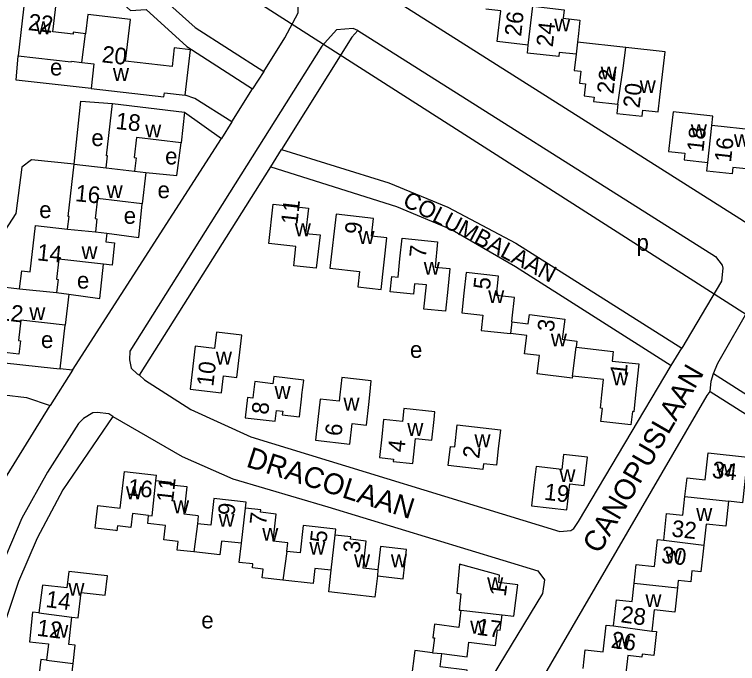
# Model space of a CAD drawing. Extents: x 161936 to 163647, y 386450 to 388633.
# Drawn here: x 162752.9 to 162926.6, y 386685.5 to 386841.4 of the extents above; entities that cross this region are included whole.
import ezdxf

# ---------------------------------------------------------------- set-up
doc = ezdxf.new("R2010")
doc.units = 0
for name, color, linetype in [('BLT_Basislijn', 7, 'Continuous'), ('BLT_Bebouwing', 7, 'Continuous'), ('BLT_Centroide', 7, 'Continuous'), ('BLT_Hoogspanningsmast_en_leidingen', 7, 'Continuous'), ('BLT_Huisnummer', 7, 'Continuous'), ('BLT_Huisnummer_ tussenligend', 7, 'Continuous'), ('BLT_Onderverdeling_panden', 7, 'Continuous'), ('BLT_Straatnaam', 7, 'Continuous'), ('BLT_Straatnaam_verkleind', 7, 'Continuous')]:
    doc.layers.add(name, color=color, linetype=linetype)

msp = doc.modelspace()

# ---------------------------------------------------------------- linework, layer by layer
at = {"layer": 'BLT_Basislijn'}
for p, q in [((162812.79, 386827.68), (162810.14, 386823.51)), ((162805.16, 386815.58), (162810.14, 386823.51)), ((162793.8, 386817.95), (162802.65, 386811.57)), ((162805.16, 386815.58), (162802.65, 386811.57)), ((162766.85, 386755.96), (162802.65, 386811.57)), ((162814.47, 386804.76), (162817.03, 386808.96)), ((162782.93, 386754.74), (162814.47, 386804.76)), ((162763.95, 386756.26), (162765.14, 386766.74)), ((162910.66, 386757.07), (162913.17, 386761.25)), ((162766.85, 386755.96), (162761.5, 386747.49)), ((162766.85, 386755.96), (162763.95, 386756.26)), ((162920.79, 386755.11), (162990.3, 386711.09))]:
    msp.add_line(p, q, dxfattribs=at)
for points in [[(162936.8, 386857.14), (162935.32, 386858.78), (162933.64, 386862.63), (162935.1, 386879.01), (162937.86, 386902.98), (162937.81, 386905.48), (162935.4, 386907.84), (162904.46, 386923.62), (162901.57, 386924.93), (162898.79, 386924.8), (162897.86, 386924.36), (162886.94, 386910.11), (162842.13, 386849.46), (162842.02, 386847.45), (162842.46, 386846.29), (162843.42, 386845.43), (162927.11, 386792.36), (162929.58, 386790.79)], [(162764.7, 386883.35), (162761.89, 386878.93), (162762.37, 386864.79), (162781.5, 386847.61), (162782.13, 386847.17), (162786.38, 386847.26), (162796.3, 386838.28), (162812.79, 386827.68)], [(162812.79, 386827.68), (162817.86, 386835.81), (162821.06, 386841.79), (162821, 386845.16), (162820.58, 386846.26), (162818.29, 386849.14), (162764.7, 386883.35)], [(162759.38, 386861.14), (162764.81, 386856.95), (162780.78, 386842.31), (162784.57, 386842.55), (162794.31, 386833.67), (162810.14, 386823.51)], [(162835.41, 386837.55), (162834.27, 386838.02), (162830.29, 386837.68), (162826.79, 386833.75), (162780.68, 386760.55), (162780.59, 386758.42), (162781, 386756.44), (162782.41, 386755.03), (162782.93, 386754.74)], [(162835.41, 386837.55), (162833.98, 386835.94), (162817.03, 386808.96)], [(162835.41, 386837.55), (162921.26, 386783.25), (162922.87, 386781.16), (162923.08, 386780.45), (162922.76, 386777.33), (162913.17, 386761.25)], [(162771.34, 386823.63), (162753.36, 386825.59), (162753.86, 386831.46)], [(162805.16, 386815.58), (162796.23, 386821.24), (162793.92, 386822)], [(162767.29, 386805.44), (162768.91, 386820.58), (162776.51, 386819.97)], [(162784.51, 386803.46), (162791.97, 386802.73), (162792.94, 386810.58)], [(162817.03, 386808.96), (162842.87, 386800.98), (162857.03, 386795.09), (162873.33, 386786.43), (162913.17, 386761.25)], [(162767.29, 386805.44), (162757.02, 386806.44), (162754.73, 386804.72), (162753.3, 386793.58), (162740.88, 386774.54), (162739.9, 386760.72), (162741.39, 386758.8), (162745.4, 386758.23), (162746.76, 386758.08)], [(162814.47, 386804.76), (162844.71, 386795.25), (162858.05, 386789.62), (162873.26, 386780.84), (162910.66, 386757.07)], [(162775.15, 386788.83), (162782.77, 386787.83), (162783.63, 386795.93)], [(162766.01, 386774.23), (162773.43, 386773.18), (162774.29, 386781.41)], [(162920.79, 386755.11), (162921.83, 386757.64), (162930.08, 386772.01), (162932.53, 386774.04), (162936.13, 386773.99), (162999.95, 386732.91), (163001.7, 386730.64), (163001.7, 386727.45), (162990.3, 386711.09)], [(162746.76, 386758.08), (162762.29, 386756.42), (162763.95, 386756.26)], [(162782.93, 386754.74), (162784.14, 386753.62), (162795.28, 386746.49), (162809.67, 386739.93), (162883.93, 386717.19), (162886.57, 386717.43), (162887.27, 386717.9), (162888.41, 386719.58), (162910.66, 386757.07)], [(162920.03, 386750.79), (162920.27, 386753.27), (162920.79, 386755.11)], [(162790.57, 386600.78), (162790.73, 386604.36), (162795.98, 386649.72), (162796.62, 386650.92), (162798.46, 386652.65), (162801.59, 386653.16), (162862.7, 386652.56), (162919.26, 386749.89), (162920.03, 386750.79)], [(162920.03, 386750.79), (162979.99, 386712.91), (162982.39, 386711.29), (162982.96, 386709.97), (162926.1, 386645.24), (162880.32, 386594.41)], [(162750.43, 386750), (162755.86, 386749.4), (162761.5, 386747.49)], [(162728.43, 386670.51), (162736.88, 386695.49), (162740.37, 386707.4), (162746.01, 386721.18), (162749.44, 386728.03), (162761.5, 386747.49)], [(162776.6, 386744.83), (162775.59, 386745.44), (162772.77, 386745.82), (162771.8, 386745.7), (162769.54, 386744.35), (162768.33, 386743.18), (162760.9, 386731.43), (162754.74, 386720.41), (162748.33, 386705.49), (162725.09, 386634.99), (162722.73, 386620.46), (162722.23, 386607.04), (162723.34, 386603.79), (162724.64, 386602.11), (162726.53, 386600.36), (162729.65, 386599.25), (162771.09, 386596.47), (162775.81, 386597.36), (162778.89, 386601.28)], [(162776.6, 386744.83), (162764.56, 386727.23), (162758.39, 386715.61), (162753.9, 386705.17), (162742.91, 386672.59)], [(162776.6, 386744.83), (162793.21, 386735.25), (162805.37, 386729.84), (162828.22, 386723.15), (162878.61, 386707.72), (162880.2, 386705.59), (162879.76, 386702.34), (162857.19, 386665.08), (162855.02, 386663.16), (162851.68, 386662.44), (162793.61, 386662.98)]]:
    msp.add_lwpolyline(points, dxfattribs=at)
at = {"layer": 'BLT_Bebouwing'}
for p, q in [((162755.84, 386848.89), (162753.86, 386831.46)), ((162899.74, 386833.48), (162888.13, 386834.76)), ((162776.51, 386819.97), (162793.8, 386817.95)), ((162793.8, 386817.95), (162792.94, 386810.58)), ((162920.43, 386814.75), (162920.68, 386816.96)), ((162931.98, 386813.46), (162920.43, 386814.75)), ((162767.29, 386805.44), (162774.94, 386804.55)), ((162781.79, 386803.78), (162784.51, 386803.46)), ((162784.51, 386803.46), (162783.63, 386795.93)), ((162772.37, 386789.15), (162775.15, 386788.83)), ((162763.07, 386774.58), (162766.01, 386774.23)), ((162766.01, 386774.23), (162765.14, 386766.74)), ((162786.93, 386729.4), (162787.08, 386730.76)), ((162808.42, 386722.81), (162808.58, 386724.27)), ((162797.08, 386721), (162796.86, 386719.06))]:
    msp.add_line(p, q, dxfattribs=at)
for points in [[(162770.02, 386836.77), (162767.07, 386837.1), (162767.02, 386836.66), (162762.16, 386837.21), (162763.4, 386848.03), (162755.84, 386848.89)], [(162876.33, 386834.04), (162868.88, 386834.89), (162869.72, 386842.26), (162866.14, 386842.66)], [(162877.39, 386843.36), (162884.91, 386842.51), (162884.68, 386840.48), (162888.73, 386840.02), (162888.36, 386836.79), (162888.13, 386834.77)], [(162793.92, 386822), (162795.18, 386832.93), (162791.3, 386833.37), (162790.79, 386828.92), (162779.64, 386830.2), (162780.78, 386840.22), (162770.55, 386841.39), (162770.02, 386836.77)], [(162887.79, 386831.82), (162883.77, 386832.28), (162883.65, 386831.26), (162876.11, 386832.12), (162876.33, 386834.04)], [(162897.83, 386819.81), (162897.58, 386817.61), (162903.66, 386816.93), (162903.83, 386818.41), (162907.55, 386817.99), (162907.95, 386821.51), (162909.17, 386832.44), (162899.74, 386833.48)], [(162753.86, 386831.46), (162766.59, 386830.01), (162766.61, 386830.18), (162769.15, 386829.89)], [(162887.79, 386831.82), (162887.35, 386827.94), (162888.98, 386827.75), (162888.66, 386824.86), (162890.05, 386824.71), (162889.77, 386821.81), (162892.12, 386821.55), (162891.99, 386820.46), (162897.83, 386819.81)], [(162769.15, 386829.89), (162772.01, 386829.56), (162771.34, 386823.63)], [(162771.34, 386823.63), (162788.85, 386821.64), (162788.96, 386822.57), (162793.92, 386822)], [(162774.94, 386804.55), (162775.27, 386807.44), (162775.05, 386807.47), (162776.51, 386819.97)], [(162920.68, 386816.96), (162911.1, 386818.02), (162910.43, 386811.98), (162910.04, 386808.48), (162913.9, 386808.05), (162913.73, 386806.5), (162919.45, 386805.87)], [(162792.94, 386810.58), (162782.27, 386811.82), (162781.71, 386807), (162782.16, 386806.94), (162781.79, 386803.78)], [(162765.7, 386789.82), (162766.05, 386792.83), (162765.82, 386792.85), (162767.29, 386805.44)], [(162930.94, 386804.04), (162925.45, 386804.65), (162925.28, 386803.12), (162919.22, 386803.79), (162919.45, 386805.87)], [(162783.63, 386795.93), (162772.89, 386797.18), (162772.33, 386792.35), (162772.74, 386792.3), (162772.37, 386789.15)], [(162820, 386781.03), (162820.51, 386785.65), (162814.05, 386786.37), (162815.09, 386795.8), (162823.54, 386794.86), (162822.87, 386788.81), (162826.32, 386788.43), (162825.43, 386780.43), (162820, 386781.03)], [(162842.38, 386787.74), (162838.71, 386788.15), (162839.19, 386792.4), (162830.16, 386793.42), (162828.7, 386780.49), (162835.83, 386779.68), (162835.4, 386775.93), (162840.97, 386775.3), (162842.38, 386787.74)], [(162754.19, 386775.52), (162754.69, 386779.84), (162756.68, 386779.61), (162757.98, 386790.73), (162765.7, 386789.82)], [(162775.15, 386788.83), (162774.91, 386786.74), (162777, 386786.5), (162776.37, 386781.16), (162774.29, 386781.41)], [(162856.98, 386775.39), (162856.44, 386770.1), (162851.27, 386770.63), (162851.86, 386776.43), (162849.03, 386776.72), (162848.78, 386774.22), (162843.16, 386774.79), (162843.53, 386778.42), (162845.06, 386778.26), (162845.51, 386782.66), (162846.02, 386787.64), (162854.54, 386786.77), (162853.93, 386780.73), (162857.49, 386780.37), (162856.98, 386775.39)], [(162774.29, 386781.41), (162763.59, 386782.65), (162763.02, 386777.8), (162763.44, 386777.75), (162763.07, 386774.58)], [(162872.48, 386768.42), (162873.04, 386773.39), (162868.69, 386773.88), (162869.21, 386778.56), (162861.44, 386779.43), (162860.89, 386774.46), (162860.36, 386769.71), (162865.45, 386769.14), (162865.04, 386765.5), (162872.07, 386764.72)], [(162747.11, 386760.63), (162747.46, 386763.64), (162747.21, 386763.67), (162748.67, 386776.16), (162754.19, 386775.52)], [(162765.14, 386766.74), (162754.49, 386767.99), (162753.92, 386763.08), (162754.36, 386763.03), (162753.99, 386759.82), (162747.11, 386760.63)], [(162872.39, 386767.55), (162876.34, 386767.08), (162876.63, 386769.32), (162885.11, 386768.23), (162884.48, 386763.36), (162888, 386762.91), (162887.81, 386761.44)], [(162872.39, 386767.55), (162872.48, 386768.42)], [(162795.11, 386751.39), (162802.67, 386750.51), (162803.14, 386754.59), (162806.35, 386754.22), (162807.53, 386764.39), (162801.45, 386765.09), (162801, 386761.19), (162796.3, 386761.74), (162795.11, 386751.39)], [(162886.91, 386754.49), (162886.85, 386754.02), (162878.47, 386755.1), (162879.03, 386759.44), (162875.42, 386759.9), (162875.98, 386764.28), (162872.07, 386764.72)], [(162887.81, 386761.44), (162896.74, 386760.46), (162896.49, 386758.15), (162902.9, 386757.45), (162902.09, 386750)], [(162821.95, 386749.73), (162821.98, 386750), (162822.41, 386753.56), (162815.2, 386754.42), (162814.99, 386752.68), (162810.68, 386753.19), (162810.3, 386750), (162810.21, 386749.22), (162808.94, 386749.37), (162808.37, 386744.54), (162815.53, 386743.69), (162815.84, 386746.29), (162817.35, 386746.11), (162817.25, 386745.25), (162821.36, 386744.76), (162821.95, 386749.73)], [(162838, 386747.73), (162838.25, 386750), (162838.62, 386753.38), (162831.56, 386754.16), (162831.1, 386750), (162830.94, 386748.5), (162826.35, 386749.01), (162825.81, 386744.07), (162825.26, 386739.1), (162833.5, 386738.2), (162834.04, 386743.13), (162837.45, 386742.76), (162838, 386747.73)], [(162902.09, 386750), (162901.65, 386745.96), (162901.36, 386745.99), (162900.93, 386742.82), (162893.76, 386743.66), (162894.12, 386746.77), (162893.68, 386746.83), (162894.02, 386750), (162894.43, 386753.67), (162886.91, 386754.49)], [(162853.72, 386744.1), (162853.92, 386745.94), (162846.46, 386746.75), (162846.12, 386743.6), (162841.59, 386744.09), (162841.14, 386739.93), (162840.6, 386734.96), (162843.97, 386734.6), (162843.91, 386734.05), (162848.59, 386733.54), (162849.24, 386739.55), (162853.18, 386739.13), (162853.72, 386744.1)], [(162869.65, 386741.58), (162869.13, 386737.05), (162868.67, 386733.13), (162865.61, 386733.48), (162865.45, 386732.11), (162857.12, 386733.08), (162857.65, 386737.64), (162858.67, 386737.52), (162859.28, 386742.78), (162869.65, 386741.58)], [(162884.81, 386735.73), (162884.39, 386732.09), (162878.21, 386732.8), (162877.7, 386728.35), (162877.13, 386723.38), (162885.58, 386722.41), (162886.29, 386728.61), (162889.74, 386728.22), (162890.52, 386735.08), (162884.81, 386735.73)], [(162913.96, 386725.6), (162914.45, 386730.09), (162918.81, 386729.62), (162919.52, 386736.12), (162928.96, 386735.09), (162928.42, 386730.11), (162928.24, 386728.48), (162927.77, 386724.09), (162924.44, 386724.46)], [(162785.16, 386721.08), (162781.29, 386721.52), (162780.91, 386718.18), (162777.68, 386718.54), (162777.55, 386717.37), (162777.32, 386717.4), (162772.35, 386717.96), (162772.96, 386723.41), (162778.35, 386722.8), (162779.34, 386731.63), (162787.08, 386730.76)], [(162797.08, 386721), (162793.67, 386721.38), (162794.41, 386727.9), (162790.53, 386728.34), (162790.6, 386728.99), (162786.93, 386729.4)], [(162808.58, 386724.27), (162800.81, 386725.14), (162800.08, 386718.69), (162796.86, 386719.06)], [(162908.85, 386715.14), (162909.55, 386721.54), (162913.47, 386721.11), (162913.96, 386725.6)], [(162818.34, 386712.42), (162818.57, 386714.45), (162815.05, 386714.85), (162815.79, 386721.39), (162812.06, 386721.81), (162812.13, 386722.4), (162808.42, 386722.81)], [(162924.44, 386724.46), (162923.79, 386718.45), (162919.02, 386718.97), (162918.46, 386713.89)], [(162795.98, 386712.28), (162792.01, 386712.73), (162792.24, 386714.78), (162788.78, 386715.17), (162789.18, 386718.65), (162784.94, 386719.12), (162785.16, 386721.08)], [(162829.96, 386716.35), (162830.12, 386717.74), (162822.26, 386718.62), (162821.52, 386712.06), (162818.34, 386712.42)], [(162840.23, 386707.97), (162836.69, 386708.37), (162837.43, 386714.9), (162833.65, 386715.33), (162833.72, 386715.93), (162829.96, 386716.35)], [(162807.46, 386714.36), (162802.65, 386714.9), (162802.28, 386711.57), (162795.98, 386712.28)], [(162817.39, 386705.52), (162812.44, 386706.08), (162812.68, 386708.18), (162810.08, 386708.47), (162810.19, 386709.4), (162806.94, 386709.77), (162807.46, 386714.36)], [(162901.78, 386704.81), (162902.27, 386709.25), (162906.62, 386708.78), (162907.33, 386715.3), (162908.85, 386715.14)], [(162840.1, 386706.54), (162846.31, 386705.83), (162847.1, 386712.87)], [(162847.1, 386712.87), (162840.82, 386713.58), (162840.23, 386707.97)], [(162918.46, 386713.89), (162917.76, 386707.49), (162915.63, 386707.72), (162915.34, 386705.11), (162912.33, 386705.44), (162912.13, 386703.68)], [(162859.8, 386709.35), (162859.14, 386702.36), (162860.15, 386702.25), (162859.73, 386698.34), (162860.15, 386698.29)], [(162870.02, 386697.2), (162872.84, 386696.83), (162873.84, 386704.38), (162869.23, 386704.97), (162869.43, 386706.71), (162859.8, 386709.35)], [(162766.7, 386696.65), (162768.21, 386696.48), (162768.92, 386702.55), (162774.74, 386701.87), (162775.28, 386706.52), (162772.97, 386706.79), (162770.96, 386707.03), (162765.99, 386707.61), (162765.53, 386703.65), (162759.64, 386704.34), (162758.82, 386697.65)], [(162829, 386707.89), (162825.09, 386708.33), (162824.68, 386704.7), (162817.39, 386705.52)], [(162840.1, 386706.54), (162839.52, 386701.44), (162828.41, 386702.69), (162829, 386707.89)], [(162896.79, 386694.54), (162897.48, 386700.79), (162901.3, 386700.37), (162901.78, 386704.81)], [(162912.13, 386703.68), (162911.5, 386697.86), (162906.57, 386698.41), (162906, 386693.29)], [(162758.82, 386697.65), (162757.29, 386697.81), (162756.53, 386690.68), (162761.09, 386690.2), (162760.67, 386686.33)], [(162860.15, 386698.29), (162859.63, 386694.16), (162853.8, 386694.91), (162853.39, 386691.67), (162853.77, 386691.62), (162853.31, 386688.09)], [(162855.54, 386687.87), (162861.62, 386687.09), (162862.07, 386690.62), (162868.48, 386689.79), (162868.97, 386693.61), (162869.55, 386693.53), (162870.02, 386697.2)], [(162767.03, 386685.52), (162767.49, 386689.87), (162765.99, 386690.03), (162766.7, 386696.65)], [(162889.49, 386684.3), (162889.99, 386688.79), (162894.3, 386688.31), (162895.02, 386694.74), (162896.79, 386694.54)], [(162906, 386693.29), (162907.12, 386693.16), (162906.49, 386687.45), (162903.7, 386687.76), (162903.62, 386687.03), (162900.24, 386687.41), (162899.77, 386683.16)], [(162853.31, 386688.09), (162849.1, 386688.63), (162848.21, 386681.7), (162851.73, 386681.25), (162851.23, 386677.32)], [(162760.67, 386686.33), (162759.24, 386686.48), (162758.81, 386682.45), (162753.56, 386683.02), (162752.73, 386675.3), (162762.24, 386674.28), (162762.8, 386679.53), (162766.34, 386679.15), (162766.88, 386684.12), (162767.03, 386685.52)], [(162857.8, 386676.48), (162860.67, 386676.11), (162861.66, 386683.86), (162855.13, 386684.7), (162855.54, 386687.87)]]:
    msp.add_lwpolyline(points, dxfattribs=at)
at = {"layer": 'BLT_Hoogspanningsmast_en_leidingen'}
msp.add_line((162756.36, 386879.56), (163001.94, 386722.51), dxfattribs=at)
at = {"layer": 'BLT_Onderverdeling_panden'}
for p, q in [((162876.33, 386834.04), (162877.39, 386843.36)), ((162769.15, 386829.89), (162770.02, 386836.77)), ((162888.13, 386834.76), (162887.79, 386831.82)), ((162919.45, 386805.87), (162920.43, 386814.75)), ((162774.94, 386804.55), (162781.79, 386803.78)), ((162765.7, 386789.82), (162772.37, 386789.15)), ((162754.19, 386775.52), (162763.07, 386774.58)), ((162872.39, 386767.55), (162872.07, 386764.72)), ((162886.91, 386754.49), (162887.81, 386761.44)), ((162913.96, 386725.6), (162924.44, 386724.46)), ((162829, 386707.89), (162829.96, 386716.35)), ((162908.85, 386715.14), (162918.46, 386713.89)), ((162818.34, 386712.42), (162817.39, 386705.52)), ((162840.23, 386707.97), (162840.1, 386706.54)), ((162901.78, 386704.81), (162912.13, 386703.68)), ((162758.82, 386697.65), (162766.7, 386696.65)), ((162860.15, 386698.29), (162870.02, 386697.2)), ((162896.79, 386694.54), (162906, 386693.29)), ((162853.31, 386688.09), (162855.54, 386687.87)), ((162760.67, 386686.33), (162767.03, 386685.52))]:
    msp.add_line(p, q, dxfattribs=at)
for points in [[(162897.83, 386819.81), (162899.14, 386828.5), (162899.74, 386833.48)], [(162785.16, 386721.08), (162785.97, 386720.93), (162786.93, 386729.4)], [(162807.46, 386714.36), (162808.42, 386722.81)], [(162796.86, 386719.06), (162795.98, 386712.28)]]:
    msp.add_lwpolyline(points, dxfattribs=at)

# ---------------------------------------------------------------- texts
at = {"layer": 'BLT_Centroide'}
for s, p in [('w', (162757.97, 386836.63)), ('w', (162882.56, 386837.31)), ('e', (162761.47, 386826.74)), ('w', (162893.72, 386825.77)), ('w', (162776.59, 386825.42)), ('w', (162903.09, 386822.52)), ('w', (162784.33, 386811.88)), ('w', (162915.36, 386811.92)), ('e', (162771.41, 386809.78)), ('w', (162925.7, 386809.56)), ('e', (162789.12, 386805.37)), ('w', (162775.07, 386797.28)), ('e', (162787.3, 386797.25)), ('e', (162758.88, 386792.49)), ('e', (162779.18, 386791.1)), ('w', (162820.26, 386788.12)), ('w', (162835.53, 386786.27)), ('p', (162902.31, 386784.61)), ('w', (162769.03, 386782.66)), ('w', (162851.23, 386778.88)), ('e', (162767.95, 386775.54)), ('w', (162866.7, 386772.08)), ('w', (162756.5, 386768)), ('w', (162881.75, 386761.66)), ('e', (162759.31, 386761.27)), ('e', (162847.92, 386758.9)), ('w', (162801.31, 386757.31)), ('w', (162896.5, 386752.34)), ('w', (162815.39, 386749.06)), ('w', (162831.94, 386746.25)), ('w', (162847.27, 386740.17)), ('w', (162863.4, 386737.44)), ('w', (162921.47, 386730.34)), ('w', (162883.8, 386729.06)), ('w', (162779.72, 386724.95)), ('w', (162791.02, 386721.59)), ('w', (162916.65, 386719.75)), ('w', (162801.94, 386718.33)), ('w', (162812.44, 386715)), ('w', (162823.75, 386711.64)), ('w', (162909.31, 386709.53)), ('w', (162834.48, 386708.61)), ('w', (162843.33, 386708.62)), ('w', (162866.45, 386703.12)), ('w', (162765.89, 386701.75)), ('w', (162904.46, 386699.06)), ('e', (162797.81, 386693.92)), ('w', (162862.38, 386692.69)), ('w', (162762.02, 386691.7)), ('w', (162896.92, 386689))]:
    msp.add_text(s, height=4, dxfattribs=at).set_placement(p)
at = {"layer": 'BLT_Huisnummer'}
for s, rotation, p in [('22', 353.5062, (162756.09, 386837.65)), ('26', 83.5242, (162874.59, 386835.99)), ('24', 83.513, (162882.2, 386833.46)), ('20', 353.5108, (162773.79, 386829.93)), ('22', 83.5776, (162896.77, 386822.16)), ('20', 83.5776, (162903.04, 386818.77)), ('18', 353.5672, (162777.1, 386813.93)), ('18', 83.6819, (162918.37, 386808.24)), ('16', 83.6846, (162925, 386805.76)), ('16', 354.2375, (162767.41, 386796.56)), ('11', 83.6567, (162820.88, 386790.79)), ('9', 83.5687, (162836.21, 386788.44)), ('14', 354.1503, (162758.24, 386782.36)), ('7', 84.1913, (162851.7, 386782.8)), ('5', 83.6497, (162867.09, 386775.16)), ('12', 353.3365, (162748.9, 386768.08)), ('3', 82.6794, (162882.43, 386765)), ('10', 83.4068, (162800.67, 386751.91)), ('1', 83.7713, (162899.9, 386754.44)), ('8', 83.2246, (162813.84, 386745.16)), ('6', 83.7299, (162831.46, 386739.99)), ('4', 83.8179, (162846.55, 386736.11)), ('2', 83.3759, (162864.54, 386734.59)), ('34', 353.7792, (162920.31, 386730.12)), ('16', 353.5511, (162780, 386725.94)), ('11', 83.5595, (162791.01, 386724.04)), ('19', 353.4544, (162880.02, 386724.84)), ('9', 83.5513, (162805.75, 386720.89)), ('7', 83.5531, (162813.35, 386718.6)), ('5', 83.5551, (162827.86, 386714.34)), ('3', 83.5677, (162835.8, 386711.87)), ('1', 82.4482, (162870.9, 386701.45)), ('14', 352.7408, (162760.3, 386699.07)), ('28', 352.2237, (162898.4, 386695.42)), ('12', 352.7441, (162758.18, 386692.18)), ('17', 352.6859, (162863.78, 386692.41))]:
    msp.add_text(s, height=4, rotation=rotation, dxfattribs=at).set_placement(p)
at = {"layer": 'BLT_Huisnummer_ tussenligend'}
for s, rotation, p in [('32', 353.7801, (162910.6, 386716.01)), ('30', 353.7801, (162908.15, 386709.7)), ('26', 352.2237, (162896.04, 386689.29))]:
    msp.add_text(s, height=4, rotation=rotation, dxfattribs=at).set_placement(p)
at = {"layer": 'BLT_Straatnaam'}
for s, rotation, p in [('CANOPUSLAAN', 59.9847, (162893.4, 386711.61)), ('DRACOLAAN', 342.232, (162808.36, 386732.84))]:
    msp.add_text(s, height=5, rotation=rotation, dxfattribs=at).set_placement(p)
at = {"layer": 'BLT_Straatnaam_verkleind'}
msp.add_text('COLUMBALAAN', height=3.9999, rotation=332.3659, dxfattribs=at).set_placement((162845.89, 386795.63))

doc.saveas('drawing.dxf')
